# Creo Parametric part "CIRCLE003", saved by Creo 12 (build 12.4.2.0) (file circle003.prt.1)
Units: Custom; MM, KILOGRAM, SECS

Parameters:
  PTC_WM_ITERATION = "0"
  PTC_WM_VERSION = "-.0"
  PTC_WM_LIFECYCLE_STATE = "In Work"
  PTC_WM_LIFECYCLE = "MO_CADDocument"
  PTC_WM_CREATED_BY = "Maximilian Roepper (Z0017RMS: MO)"
  PTC_WM_CREATED_ON = "18-Sep-26 11:36:42 AM"
  PTC_WM_MODIFIED_BY = "Maximilian Roepper (Z0017RMS: MO)"
  PTC_WM_MODIFIED_ON = "18-Sep-26 11:36:46 AM"
  PDMLINKNUMBER = "PDM000071455272"
  PTC_WM_NAME = "circle003.prt"
  PTC_WM_NUMBER = "PDM000071455272"

Other parameters: WEIGHT, WEIGHT_FACTOR, WEIGHT_ADD, _MASS_TEMP, _DIFF_TEMP, MC_ERRORS, SUPPLIER

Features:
  1. coordinate system
  2. datum plane "PRT_YZ"
  3. datum plane "PRT_XY"
  4. datum plane "PRT_XZ"
  5. coordinate system
  6. datum axis
  7. datum axis
  8. datum axis
  9. coordinate system
  10. imported feature
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
Other named items: PRT, SIEMENS_MO, DRW_VIEW_ORG, PRT_X, PRT_Y, PRT_Z, CS0, ROUGH_GROB

Layers: 00_STD_CSYS-KSYS, 01_STD_PLANES-EBENEN, 02_STD_AXES-ACHSEN, 03_STD_CSYS-KSYS, 24_IMPORT_FEAT-IMPORT_KE

Surfaces: 2 cylinder, 2 plane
